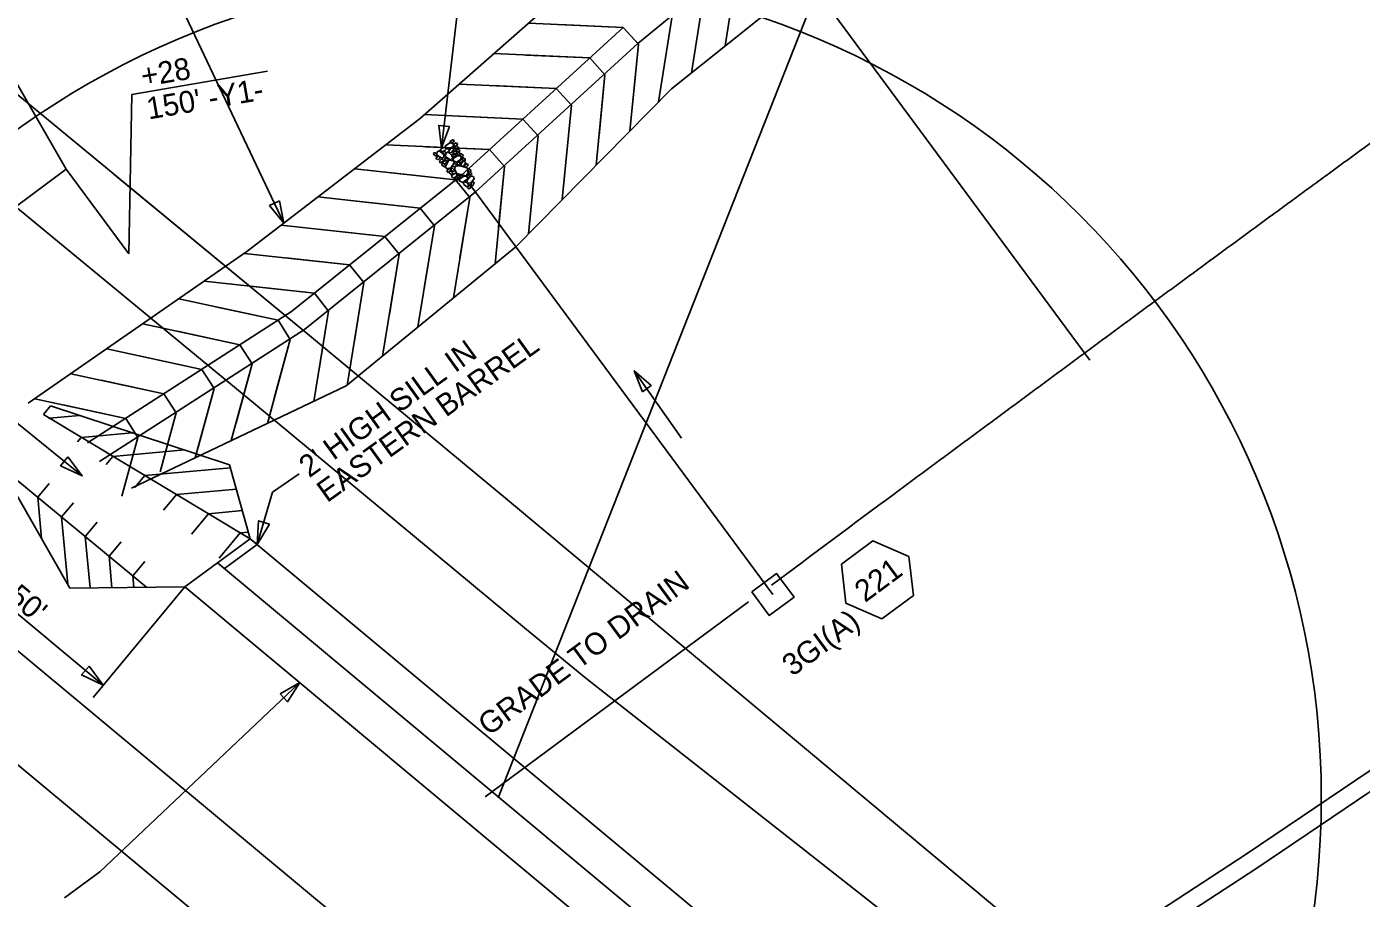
# Model space of a CAD drawing. Extents: x 2384780 to 2405432, y 547869 to 573706.
# Drawn here: x 2392222.8 to 2392527.6, y 553317.4 to 553516.3 of the extents above; entities that cross this region are included whole.
import ezdxf

# ---------------------------------------------------------------- set-up
doc = ezdxf.new("R2010")
doc.units = 0
for name, color, linetype in [('Old_Level_1', 7, 'Continuous'), ('Old_Level_16', 7, 'Continuous'), ('Old_Level_18', 7, 'Continuous'), ('Old_Level_19', 7, 'Continuous'), ('Old_Level_23', 7, 'Continuous'), ('Old_Level_5', 7, 'Continuous'), ('Old_Level_63', 7, 'Continuous'), ('Old_Level_9', 7, 'Continuous'), ('Prop Buffer Zone 1', 7, 'Continuous'), ('Prop Buffer Zone 2', 7, 'Continuous'), ('Prop Special Cut Base Ditch Detail CELL', 7, 'Continuous')]:
    doc.layers.add(name, color=color, linetype=linetype)

# ---------------------------------------------------------------- blocks, each defined once
blk = doc.blocks.new('IN')
at = {"layer": 'Old_Level_9'}
blk.add_lwpolyline([(-0.07025, 0.067), (0.07025, 0.067), (0.07025, -0.067), (-0.07025, -0.067)], close=True, dxfattribs=at)
blk = doc.blocks.new('RIPRAP')
at = {"layer": 'Old_Level_1'}
for points in [[(-0.002, -0.00625), (-0.00625, -0.00775), (-0.016, -0.0125), (-0.02, -0.00675), (-0.02, -0.003), (-0.008, 0.00275), (-0.002, -0.00025), (-0.002, -0.00625)], [(0.01825, -0.00325), (0.01375, -0.005), (0.00325, -0.00975), (0.00025, -0.00375), (0, 0), (0.01125, 0.005), (0.018, 0.00275), (0.01825, -0.00325)], [(-0.03675, -0.07275), (-0.04075, -0.06825), (-0.04325, -0.0585), (-0.0395, -0.054), (-0.035, -0.054), (-0.031, -0.0665), (-0.033, -0.0705), (-0.03675, -0.07275)], [(-0.0305, -0.05975), (-0.035, -0.05625), (-0.0375, -0.0465), (-0.033, -0.042), (-0.02925, -0.042), (-0.02475, -0.05375), (-0.02675, -0.05825), (-0.0305, -0.05975)], [(-0.00025, -0.11525), (-0.0145, -0.10575), (-0.0355, -0.078), (-0.0255, -0.056), (-0.00975, -0.051), (0.01725, -0.08475), (0.01525, -0.10425), (0.002, -0.11775)], [(-0.0345, -0.0215), (-0.0265, -0.01775), (-0.007, -0.01125), (0.00375, -0.02075), (0.003, -0.0315), (-0.02075, -0.03775), (-0.03225, -0.032), (-0.0345, -0.024)], [(-0.0275, -0.0395), (-0.023, -0.03925), (-0.014, -0.039), (-0.0115, -0.045), (-0.0115, -0.04875), (-0.0235, -0.049), (-0.0295, -0.04475), (-0.0275, -0.0395)], [(-0.0095, -0.039), (0.00025, -0.0365), (0.0205, -0.036), (0.02775, -0.0495), (0.024, -0.05775), (-0.00075, -0.05675), (-0.009, -0.0485), (-0.0095, -0.039)], [(0.009, -0.07425), (0.0045, -0.07075), (0.00225, -0.061), (0.00625, -0.05625), (0.01, -0.057), (0.01425, -0.06825), (0.01275, -0.072), (0.009, -0.07425)], [(0.012, -0.0355), (0.00825, -0.0295), (0.0035, -0.01775), (0.01025, -0.00925), (0.01825, -0.009), (0.0225, -0.027), (0.01875, -0.033), (0.012, -0.0355)], [(0.01975, -0.07925), (0.01525, -0.07475), (0.01375, -0.06525), (0.01725, -0.0605), (0.02175, -0.0605), (0.02575, -0.07325), (0.0235, -0.077), (0.01975, -0.07925)], [(0.03125, -0.0765), (0.0265, -0.073), (0.02425, -0.06325), (0.0285, -0.0585), (0.03225, -0.05925), (0.03625, -0.0705), (0.035, -0.07425), (0.03125, -0.0765)], [(-0.046, -0.12775), (-0.0505, -0.12425), (-0.053, -0.1145), (-0.0485, -0.11), (-0.04475, -0.11), (-0.04, -0.12175), (-0.04225, -0.12625), (-0.046, -0.12775)], [(-0.0485, -0.08525), (-0.0425, -0.0835), (-0.03275, -0.0825), (-0.0305, -0.08925), (-0.03175, -0.0945), (-0.0445, -0.09325), (-0.049, -0.089), (-0.0485, -0.08525)], [(-0.046, -0.1025), (-0.04025, -0.098), (-0.02675, -0.09375), (-0.02, -0.09975), (-0.02, -0.10575), (-0.03625, -0.11225), (-0.044, -0.1085), (-0.046, -0.1025)], [(-0.023, -0.1195), (-0.02725, -0.12175), (-0.037, -0.126), (-0.041, -0.1195), (-0.041, -0.11625), (-0.029, -0.1115), (-0.02525, -0.1135), (-0.023, -0.1195)], [(-0.01575, -0.1245), (-0.02025, -0.12125), (-0.022, -0.11125), (-0.0185, -0.10675), (-0.014, -0.10675), (-0.00975, -0.1185), (-0.012, -0.123), (-0.01575, -0.1245)], [(-0.00575, -0.118), (0.00025, -0.1155), (0.0085, -0.1175), (0.0125, -0.12425), (0.01025, -0.128), (-0.00175, -0.12825), (-0.00575, -0.12175), (-0.00575, -0.118)], [(0.0225, -0.12), (0.0185, -0.11625), (0.01675, -0.10675), (0.0205, -0.102), (0.025, -0.102), (0.0285, -0.114), (0.02625, -0.11775), (0.0225, -0.12)], [(0.02025, -0.07975), (0.02825, -0.07725), (0.04025, -0.077), (0.045, -0.08725), (0.042, -0.0935), (0.02475, -0.092), (0.02025, -0.0855), (0.02025, -0.07975)], [(0.048, -0.1195), (0.04425, -0.12325), (0.036, -0.12575), (0.03, -0.122), (0.02975, -0.1155), (0.04175, -0.11375), (0.04775, -0.11575), (0.048, -0.1195)], [(0.03775, -0.114), (0.03325, -0.11025), (0.031, -0.1005), (0.035, -0.096), (0.03875, -0.09675), (0.043, -0.10775), (0.0415, -0.1115), (0.03775, -0.114)], [(-0.061, -0.17925), (-0.055, -0.17725), (-0.04525, -0.17625), (-0.043, -0.183), (-0.04425, -0.18825), (-0.057, -0.187), (-0.0615, -0.18275), (-0.061, -0.17925)], [(-0.04975, -0.14825), (-0.05425, -0.14475), (-0.05675, -0.135), (-0.05225, -0.1305), (-0.0485, -0.1305), (-0.04375, -0.14225), (-0.046, -0.14675), (-0.04975, -0.14825)], [(-0.04975, -0.17575), (-0.05375, -0.1705), (-0.05675, -0.16075), (-0.05225, -0.157), (-0.04875, -0.157), (-0.04375, -0.169), (-0.046, -0.1735), (-0.04975, -0.17575)], [(-0.032, -0.15425), (-0.03625, -0.15575), (-0.046, -0.158), (-0.0505, -0.15375), (-0.05075, -0.15075), (-0.041, -0.146), (-0.035, -0.14825), (-0.03275, -0.152)], [(-0.04275, -0.12825), (-0.03225, -0.126), (-0.012, -0.1275), (-0.00575, -0.1395), (-0.009, -0.15), (-0.033, -0.1485), (-0.04375, -0.13875), (-0.04275, -0.12825)], [(-0.0355, -0.17625), (-0.037, -0.1725), (-0.04125, -0.16275), (-0.03525, -0.158), (-0.0315, -0.158), (-0.02675, -0.17075), (-0.031, -0.174), (-0.0355, -0.17625)], [(-0.012, -0.187), (-0.01875, -0.19075), (-0.033, -0.1935), (-0.039, -0.1875), (-0.039, -0.1815), (-0.02275, -0.17675), (-0.01525, -0.17875), (-0.012, -0.187)], [(-0.0215, -0.16975), (-0.02625, -0.1655), (-0.0285, -0.15575), (-0.024, -0.15125), (-0.02025, -0.15175), (-0.01625, -0.163), (-0.01775, -0.1675), (-0.0215, -0.16975)], [(0.00075, -0.15075), (0.0045, -0.15875), (0.011, -0.179), (0.0015, -0.18875), (-0.009, -0.189), (-0.01475, -0.16525), (-0.012, -0.153), (-0.0015, -0.1515)], [(0.04, -0.14075), (0.03075, -0.14625), (0.009, -0.15575), (-0.004, -0.14175), (-0.00425, -0.132), (0.024, -0.123), (0.03825, -0.1285), (0.0425, -0.1405)], [(0.01625, -0.174), (0.0125, -0.17075), (0.009, -0.16), (0.0135, -0.1555), (0.01725, -0.15625), (0.022, -0.168), (0.02075, -0.17175), (0.01625, -0.174)], [(0.026, -0.18075), (0.03225, -0.18875), (0.03875, -0.20825), (0.02925, -0.219), (0.01875, -0.21675), (0.012, -0.193), (0.01575, -0.184), (0.026, -0.17925)], [(0.0205, -0.15575), (0.0265, -0.15325), (0.03475, -0.15525), (0.03875, -0.162), (0.0365, -0.16575), (0.0245, -0.166), (0.0205, -0.1595), (0.0205, -0.15575)], [(0.04925, -0.17425), (0.044, -0.17875), (0.03525, -0.1805), (0.02975, -0.177), (0.0295, -0.171), (0.0415, -0.16925), (0.0475, -0.1705), (0.04925, -0.17425)], [(0.043, -0.162), (0.03825, -0.1585), (0.036, -0.14875), (0.04, -0.144), (0.04375, -0.14475), (0.048, -0.15575), (0.04675, -0.1595), (0.043, -0.162)], [(-0.06725, -0.1915), (-0.06125, -0.18975), (-0.0515, -0.18875), (-0.04925, -0.1955), (-0.0505, -0.20075), (-0.06325, -0.1995), (-0.06775, -0.19525), (-0.06725, -0.1915)], [(-0.064, -0.2115), (-0.058, -0.20975), (-0.04825, -0.20875), (-0.046, -0.2155), (-0.04725, -0.22075), (-0.06, -0.2195), (-0.0645, -0.21525), (-0.064, -0.2115)], [(-0.05075, -0.19675), (-0.0405, -0.195), (-0.021, -0.194), (-0.01375, -0.208), (-0.018, -0.21775), (-0.042, -0.21675), (-0.0505, -0.20725), (-0.05075, -0.19675)], [(-0.0115, -0.204), (-0.00425, -0.2025), (0.0085, -0.20225), (0.01275, -0.21275), (0.01125, -0.2185), (-0.0075, -0.21675), (-0.01225, -0.21075), (-0.0115, -0.204)], [(0.00625, -0.2035), (0.00175, -0.19975), (-0.001, -0.19), (0.0035, -0.1855), (0.00725, -0.1855), (0.012, -0.1975), (0.01, -0.202), (0.00625, -0.2035)], [(0.0335, -0.189), (0.0395, -0.18675), (0.04775, -0.18875), (0.0515, -0.1955), (0.04925, -0.19925), (0.03725, -0.1995), (0.0335, -0.19275), (0.0335, -0.189)], [(0.04325, -0.22375), (0.0385, -0.22025), (0.03625, -0.2105), (0.0405, -0.20575), (0.04425, -0.2065), (0.0485, -0.2175), (0.047, -0.22125), (0.04325, -0.22375)]]:
    blk.add_lwpolyline(points, dxfattribs=at)

msp = doc.modelspace()

# ---------------------------------------------------------------- linework, layer by layer
at = {"layer": 'Old_Level_1'}
for p, q in [((2392317.6, 553488.71), (2392330.29, 553598.83)), ((2392385.47, 553531.72), (2392382.35, 553511.95)), ((2392377.76, 553525.42), (2392374.66, 553505.81)), ((2392370.23, 553518.79), (2392367.13, 553499.17)), ((2392393.25, 553386.74), (2392324.25, 553480)), ((2392226.65, 553427.81), (2392228.29, 553429.79)), ((2392226.65, 553427.81), (2392273.86, 553399.5)), ((2392228.02, 553426.99), (2392234.92, 553427.62)), ((2392228.29, 553429.79), (2392269.19, 553416.39)), ((2392228.02, 553426.99), (2392227.89, 553426.82)), ((2392235.29, 553422.63), (2392234.44, 553421.61)), ((2392235.29, 553422.63), (2392246.91, 553423.69)), ((2392242.55, 553418.27), (2392258.9, 553419.77)), ((2392216.83, 553416.01), (2392232.72, 553388.21)), ((2392216.83, 553416.01), (2392250.26, 553388.39)), ((2392242.55, 553418.27), (2392240.99, 553416.4)), ((2392249.82, 553413.92), (2392269.38, 553415.7)), ((2392269.19, 553416.39), (2392273.86, 553399.5)), ((2392249.82, 553413.92), (2392247.55, 553411.19)), ((2392278.97, 553410.12), (2392285.04, 553414.32)), ((2392225.37, 553408.95), (2392228, 553412.11)), ((2392257.08, 553409.56), (2392254.1, 553405.98)), ((2392257.08, 553409.56), (2392270.74, 553410.81)), ((2392275.44, 553398.18), (2392278.97, 553410.12)), ((2392225.37, 553408.95), (2392226.23, 553399.55)), ((2392230.8, 553404.46), (2392233.52, 553407.72)), ((2392230.8, 553404.46), (2392232.21, 553389.1)), ((2392236.23, 553399.98), (2392238.97, 553403.26)), ((2392264.35, 553405.2), (2392260.45, 553400.52)), ((2392264.35, 553405.2), (2392272.09, 553405.91)), ((2392271.61, 553400.85), (2392266.79, 553395.05)), ((2392271.61, 553400.85), (2392273.44, 553401.01)), ((2392201.87, 553398.04), (2392240.3, 553366.05)), ((2392236.23, 553399.98), (2392237.31, 553388.26)), ((2392241.67, 553395.49), (2392244.4, 553398.78)), ((2392258.96, 553388.48), (2392273.86, 553399.5)), ((2392267.99, 553392.67), (2392275.44, 553398.18)), ((2392273.86, 553399.5), (2392404.54, 553290.71)), ((2392241.67, 553395.49), (2392242.32, 553388.31)), ((2392247.1, 553391), (2392249.84, 553394.29)), ((2392266.41, 553393.99), (2392397.09, 553285.2)), ((2392247.1, 553391), (2392247.34, 553388.36)), ((2392258.96, 553388.48), (2392232.72, 553388.21)), ((2392258.96, 553388.48), (2392238, 553363.29)), ((2392258.96, 553388.48), (2392389.65, 553279.69)), ((2392327.54, 553340.62), (2392387.65, 553385.09)), ((2392285.18, 553366.65), (2392239.53, 553323.51)), ((2392231.5, 553317.56), (2392239.53, 553323.51))]:
    msp.add_line(p, q, dxfattribs=at)
for points in [[(2392319.42, 553493.53), (2392317.6, 553488.71), (2392316.93, 553493.82)], [(2392278.29, 553402.82), (2392275.44, 553398.18), (2392275.78, 553403.61)], [(2392266.41, 553393.99), (2392273.86, 553399.5), (2392275.44, 553398.18), (2392267.99, 553392.67)], [(2392280.69, 553364.13), (2392285.18, 553366.65), (2392282.41, 553362.31)]]:
    msp.add_lwpolyline(points, close=True, dxfattribs=at)
at = {"layer": 'Old_Level_16'}
msp.add_lwpolyline([(2392424.31, 553395.44), (2392416.1, 553399.01), (2392408.91, 553393.69), (2392409.92, 553384.79), (2392418.13, 553381.22), (2392425.32, 553386.55)], close=True, dxfattribs=at)
at = {"layer": 'Old_Level_18'}
for p, q in [((2392362.42, 553512.48), (2392401.07, 553544.3)), ((2392370.06, 553502.14), (2392409.16, 553533.36))]:
    msp.add_line(p, q, dxfattribs=at)
for points in [[(2392223.2, 553430.4), (2392273.12, 553465.04), (2392312.8, 553495.47), (2392350.48, 553528.61)], [(2392236.76, 553421.35), (2392283.34, 553451.33), (2392322.04, 553482.39), (2392359.04, 553516.17)], [(2392337.46, 553517.15), (2392359.04, 553516.17), (2392362.53, 553512.35), (2392360.59, 553492.53)], [(2392344.44, 553516.83), (2392359.04, 553516.17), (2392362.53, 553512.35), (2392361.17, 553498.5)], [(2392239.46, 553417.15), (2392286.27, 553447.27), (2392325.29, 553478.59), (2392362.42, 553512.48)], [(2392329.54, 553510.19), (2392351.41, 553509.2), (2392354.89, 553505.38), (2392352.87, 553484.71)], [(2392336.8, 553509.86), (2392351.41, 553509.2), (2392354.89, 553505.38), (2392353.54, 553491.53)], [(2392246.74, 553411.02), (2392295.81, 553434.37), (2392334.52, 553466.11), (2392370.06, 553502.14)], [(2392321.63, 553503.23), (2392343.77, 553502.22), (2392347.26, 553498.41), (2392345.15, 553476.88)], [(2392329.16, 553502.89), (2392343.77, 553502.22), (2392347.26, 553498.41), (2392345.9, 553484.56)], [(2392313.72, 553496.27), (2392336.13, 553495.25), (2392339.62, 553491.43), (2392337.43, 553469.06)], [(2392321.52, 553495.92), (2392336.13, 553495.25), (2392339.62, 553491.43), (2392338.26, 553477.58)], [(2392304.83, 553489.35), (2392328.5, 553488.28), (2392331.98, 553484.46), (2392329.8, 553462.24)], [(2392313.89, 553488.94), (2392328.5, 553488.28), (2392331.98, 553484.46), (2392330.62, 553470.61)], [(2392297.74, 553483.91), (2392320.79, 553481.38), (2392324.03, 553477.35), (2392320.3, 553454.45)], [(2392306.26, 553482.98), (2392320.79, 553481.38), (2392324.03, 553477.35), (2392321.79, 553463.62)], [(2392289.34, 553477.48), (2392312.73, 553474.91), (2392315.96, 553470.88), (2392312.2, 553447.81)], [(2392298.19, 553476.51), (2392312.73, 553474.91), (2392315.96, 553470.88), (2392313.72, 553457.14)], [(2392280.95, 553471.04), (2392304.66, 553468.44), (2392307.9, 553464.41), (2392304.11, 553441.17)], [(2392290.12, 553470.03), (2392304.66, 553468.44), (2392307.9, 553464.41), (2392305.66, 553450.67)], [(2392272.56, 553464.6), (2392296.59, 553461.97), (2392299.83, 553457.94), (2392296, 553434.46)], [(2392282.06, 553463.56), (2392296.59, 553461.97), (2392299.83, 553457.94), (2392297.59, 553444.2)], [(2392263.35, 553458.26), (2392288.53, 553455.5), (2392291.76, 553451.46), (2392288.4, 553430.84)], [(2392273.99, 553457.09), (2392288.53, 553455.5), (2392291.76, 553451.46), (2392289.53, 553437.73)], [(2392257.58, 553454.25), (2392280.24, 553449.34), (2392283.04, 553444.99), (2392277.81, 553425.8)], [(2392265.94, 553452.44), (2392280.24, 553449.34), (2392283.04, 553444.99), (2392279.38, 553431.56)], [(2392249.36, 553448.55), (2392271.54, 553443.74), (2392274.34, 553439.39), (2392269.57, 553421.88)], [(2392257.25, 553446.84), (2392271.54, 553443.74), (2392274.34, 553439.39), (2392270.68, 553425.96)], [(2392241.15, 553442.85), (2392262.85, 553438.14), (2392265.64, 553433.8), (2392261.33, 553417.96)], [(2392248.55, 553441.24), (2392262.85, 553438.14), (2392265.64, 553433.8), (2392261.99, 553420.37)], [(2392232.93, 553437.15), (2392254.15, 553432.55), (2392256.95, 553428.2), (2392253.29, 553414.77)], [(2392239.86, 553435.65), (2392254.15, 553432.55), (2392256.95, 553428.2), (2392253.29, 553414.77)], [(2392224.72, 553431.45), (2392245.45, 553426.95), (2392248.25, 553422.6), (2392244.6, 553409.17)], [(2392231.16, 553430.05), (2392245.45, 553426.95), (2392248.25, 553422.6), (2392244.6, 553409.17)]]:
    msp.add_lwpolyline(points, dxfattribs=at)
at = {"layer": 'Old_Level_19'}
msp.add_spline([(2392694.43, 553605.76), (2392690.61, 553603.18), (2392686.79, 553600.6), (2392682.97, 553598.02), (2392679.16, 553595.43), (2392675.35, 553592.83), (2392671.54, 553590.23), (2392667.73, 553587.63), (2392663.93, 553585.03), (2392660.13, 553582.41), (2392656.33, 553579.8), (2392652.54, 553577.18), (2392648.75, 553574.56), (2392644.96, 553571.93), (2392641.17, 553569.3), (2392637.39, 553566.67), (2392633.61, 553564.03), (2392629.83, 553561.39), (2392626.05, 553558.75), (2392622.28, 553556.1), (2392618.51, 553553.45), (2392614.74, 553550.79), (2392610.97, 553548.13), (2392607.21, 553545.47), (2392603.45, 553542.81), (2392599.69, 553540.14), (2392595.93, 553537.47), (2392592.18, 553534.8), (2392588.42, 553532.12), (2392584.67, 553529.44), (2392580.92, 553526.76), (2392577.17, 553524.08), (2392573.43, 553521.39), (2392569.68, 553518.7), (2392565.94, 553516.01), (2392562.2, 553513.32), (2392558.46, 553510.62), (2392554.73, 553507.92), (2392550.99, 553505.22), (2392547.26, 553502.52), (2392543.53, 553499.81), (2392539.8, 553497.1), (2392536.07, 553494.39), (2392532.34, 553491.68), (2392528.62, 553488.97), (2392524.89, 553486.25), (2392521.17, 553483.54), (2392517.45, 553480.82), (2392513.73, 553478.1), (2392510.01, 553475.38), (2392506.29, 553472.65), (2392502.57, 553469.93), (2392498.85, 553467.2), (2392495.14, 553464.48), (2392491.42, 553461.75), (2392487.71, 553459.02), (2392484, 553456.29), (2392480.29, 553453.56), (2392476.58, 553450.82), (2392472.87, 553448.09), (2392469.16, 553445.35), (2392465.45, 553442.62), (2392461.74, 553439.88), (2392458.03, 553437.15), (2392454.32, 553434.41), (2392450.62, 553431.67), (2392446.91, 553428.93), (2392443.21, 553426.19), (2392439.5, 553423.45), (2392435.79, 553420.71), (2392432.09, 553417.97), (2392428.38, 553415.23), (2392424.68, 553412.49), (2392420.98, 553409.75), (2392392.9, 553388.88)], degree=3, dxfattribs=at)
at = {"layer": 'Old_Level_23'}
msp.add_lwpolyline([(2392235.52, 553413.84), (2392214.39, 553430.86)], dxfattribs=at)
for points in [[(2392232.24, 553418.18), (2392235.52, 553413.84), (2392230.58, 553416.13)], [(2392237.08, 553370.44), (2392240.3, 553366.05), (2392235.39, 553368.42)]]:
    msp.add_lwpolyline(points, close=True, dxfattribs=at)
at = {"layer": 'Old_Level_5'}
for p, q in [((2392281.58, 553471.52), (2392238.45, 553562.34)), ((2392361.57, 553437.84), (2392372.39, 553422.48))]:
    msp.add_line(p, q, dxfattribs=at)
for points in [[(2392280.56, 553476.57), (2392281.58, 553471.52), (2392278.31, 553475.5)], [(2392363.43, 553433.03), (2392361.57, 553437.84), (2392365.47, 553434.47)]]:
    msp.add_lwpolyline(points, close=True, dxfattribs=at)
at = {"layer": 'Old_Level_63'}
for p, q in [((2392465.6, 553440.27), (2392353.49, 553591.8)), ((2392190.88, 553453.46), (2392231.87, 553483.8)), ((2392231.87, 553483.8), (2392246.15, 553464.5))]:
    msp.add_line(p, q, dxfattribs=at)
for points in [[(2392330.54, 553340.35), (2392792.97, 554511.2), (2392584.72, 554490.3)], [(2392231.87, 553483.8), (2392214.98, 553513.01), (2392182.02, 553507.32)], [(2392246.15, 553464.5), (2392246.89, 553500.86), (2392277.84, 553506.2)]]:
    msp.add_lwpolyline(points, dxfattribs=at)
msp.add_circle((2392330.54, 553340.35), 187.94, dxfattribs=at)
at = {"layer": 'Prop Buffer Zone 1'}
for points in [[(2392191.17, 553499.23), (2392275.11, 553430.09), (2392336.97, 553378.79), (2392350.49, 553367.67), (2392422.73, 553310.96)], [(2392213.98, 553379.54), (2392335.24, 553278.71), (2392375.95, 553245.44)]]:
    msp.add_lwpolyline(points, dxfattribs=at)
at = {"layer": 'Prop Buffer Zone 2'}
for points in [[(2392205.5, 553513.34), (2392287.85, 553445.51), (2392333.07, 553408.01), (2392451.67, 553309.03)], [(2392242.81, 553482.61), (2392287.85, 553445.51), (2392333.07, 553408.01)], [(2392198.55, 553366.36), (2392322.52, 553263.28), (2392364.33, 553229.11)]]:
    msp.add_lwpolyline(points, dxfattribs=at)
at = {"layer": 'Prop Special Cut Base Ditch Detail CELL'}
for points in [[(2393431.32, 553709.49), (2393357.37, 553699.67), (2393302.75, 553690.31), (2393257.86, 553681.9), (2393220.94, 553673.62), (2393177.22, 553664.1), (2393130.25, 553651.77), (2393083.63, 553636.74), (2393035.75, 553621.04), (2392997.2, 553608.43), (2392948.74, 553587.92), (2392921.95, 553579.12), (2392876.37, 553560.72), (2392828.54, 553536.35), (2392787.32, 553514.22), (2392744.89, 553491.62), (2392704.03, 553467.27), (2392661.48, 553438.97), (2392622.97, 553410.36), (2392582.55, 553381.89), (2392542.07, 553355), (2392501.34, 553327.48), (2392460.22, 553300.68), (2392415.27, 553273.9)], [(2393431.84, 553705.52), (2393357.97, 553695.72), (2393303.46, 553686.37), (2393258.66, 553677.98), (2393221.8, 553669.71), (2393178.16, 553660.21), (2393131.38, 553647.93), (2393084.86, 553632.94), (2393037, 553617.24), (2392998.6, 553604.68), (2392950.14, 553584.17), (2392923.33, 553575.36), (2392878.03, 553557.08), (2392830.39, 553532.81), (2392789.2, 553510.7), (2392746.85, 553488.14), (2392706.16, 553463.89), (2392663.78, 553435.7), (2392625.32, 553407.12), (2392584.81, 553378.59), (2392544.29, 553351.67), (2392503.55, 553324.14), (2392462.34, 553297.29), (2392417.31, 553270.46)]]:
    msp.add_lwpolyline(points, dxfattribs=at)

# ---------------------------------------------------------------- block references
at = {"layer": 'Old_Level_5'}
for name, p, xscale, yscale, rotation in [('RIPRAP', (2392324.35, 553479.96), 49.9999995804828, 49.99999958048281, -142.67353061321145), ('IN', (2392393.25, 553386.74), 50.00000000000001, 49.99999999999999, 36.49660996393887)]:
    msp.add_blockref(name, p, dxfattribs=dict(at, xscale=xscale, yscale=yscale, rotation=rotation))

# ---------------------------------------------------------------- texts
at = {"layer": 'Old_Level_1'}
for s, rotation, p in [("2' HIGH SILL IN", 35.7302, (2392287.35, 553413.26)), ('EASTERN BARREL', 35.7302, (2392291.44, 553407.58)), ("50'", 320.2239, (2392218.12, 553385.69))]:
    msp.add_text(s, height=5, rotation=rotation, dxfattribs=at).set_placement(p)
at = {"layer": 'Old_Level_16'}
msp.add_text('221', height=5, rotation=36.4924, dxfattribs=at).set_placement((2392414.28, 553384.8))
at = {"layer": 'Old_Level_5'}
for s, p in [('GRADE TO DRAIN', (2392328.31, 553354.35)), ('3GI(A)', (2392397.72, 553367.93))]:
    msp.add_text(s, height=5, rotation=36.4924, dxfattribs=at).set_placement(p)
at = {"layer": 'Old_Level_63'}
for s, p in [('+28', (2392249.4, 553502.55)), ("150' -Y1-", (2392250.68, 553495.15))]:
    msp.add_text(s, height=5, rotation=9.7834, dxfattribs=at).set_placement(p)

doc.saveas('drawing.dxf')
